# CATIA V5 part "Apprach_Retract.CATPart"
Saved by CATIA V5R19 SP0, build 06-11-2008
Part number: Part1
Bounding box of the stored display mesh (mm): x -48.65 to 48.65, y -48.65 to 48.65, z -9.277 to 47.212
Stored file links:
  G:\Podręcznik\CD\Ruchy pomocnicze\Apprach_Retract.CATPart
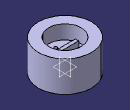
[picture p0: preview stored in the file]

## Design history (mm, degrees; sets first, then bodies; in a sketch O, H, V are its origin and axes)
Body1 (main body)
  Sketch1 on yz-plane, origin (0, 0, 0), H (0, 1, 0), V (0, 0, 1)
    point P1 (0, 21.7369)
    line L1 (0, 21.7369) -> (29.8615, 21.7369)
    line L2 (29.8615, 21.7369) -> (29.8615, 47.2124)
    line L3 (29.8615, 47.2124) -> (48.6633, 47.2124)
    line L4 (48.6633, 47.2124) -> (48.6633, -9.2767)
    line L5 (48.6633, -9.2767) -> (29.8615, -9.2767)
    point P6 (29.8615, -9.2767)
    line L6 (29.8615, -9.2767) -> (29.8615, 8.4454)
    line L7 (29.8615, 8.4454) -> (0, 8.4454)
    point P8 (0, 8.4454)
    line L8 (0, 8.4454) -> (0, 21.7369)
    coincidence: P1 V, P6 L2, P8 V
    horizontal: L1 H, L3 H, L5 H, L7 H
    vertical: L2 V, L4 V, L6 V, L8 V
  Shaft1: profile Sketch1, axis Sketch1.V, angle 360
  Sketch2 on face of Shaft1 from Sketch1.L1, origin (0, 0, 21.7369), H (1, 0, 0), V (0, 1, 0)
    circle A1 centre (0, -16.8434) radius 3.173
    point P1 (0, -16.8434)
    circle A2 centre (0, 16.8434) radius 3.173
    distance V P1 = 0
    symmetry: A1 A2 H
  Pocket1: profile Sketch2, direction (0, 0, -1), through (limit type 6)
  Sketch3 on face of Shaft1 from Sketch1.L1, origin (0, 0, 21.7369), H (1, 0, 0), V (0, 1, 0)
    line L1 (-22.2187, 3) -> (22.6128, 3)
    line L2 (22.6128, 3) -> (22.6128, -3)
    line L3 (22.6128, -3) -> (-22.2187, -3)
    line L4 (-22.2187, -3) -> (-22.2187, 3)
    reference projected circle E1 centre (0, 16.8434) radius 3.173 from edge [face of Shaft1 from Sketch1.L1 | face of Pocket1 from Sketch2.A2]
    length L2 = 6
    radius E1 = 3.173 (reference)
    distance H L1 = 3
    horizontal: L1 H, L3 H
    vertical: L2 V, L4 V
  Pad1: profile Sketch3, direction (0, 0, 1), length 10
Body2
  Sketch4 on yz-plane, origin (0, 0, 0), H (0, 1, 0), V (0, 0, 1)
    point P1 (0, 21.7369)
    line L1 (0, 21.7369) -> (29.8615, 21.7369)
    line L2 (29.8615, 21.7369) -> (29.8615, 47.2124)
    line L3 (29.8615, 47.2124) -> (48.6633, 47.2124)
    line L4 (48.6633, 47.2124) -> (48.6633, -9.2767)
    line L5 (48.6633, -9.2767) -> (29.8615, -9.2767)
    point P6 (29.8615, -9.2767)
    line L6 (29.8615, -9.2767) -> (29.8615, 8.4454)
    line L7 (29.8615, 8.4454) -> (0, 8.4454)
    point P8 (0, 8.4454)
    line L8 (0, 8.4454) -> (0, 21.7369)
    coincidence: P1 V, P6 L2, P8 V
    horizontal: L1 H, L3 H, L5 H, L7 H
    vertical: L2 V, L4 V, L6 V, L8 V
  Shaft2: profile Sketch4, axis Sketch4.V, angle 360
  Sketch5 on face of Shaft2 from Sketch4.L1, origin (0, 0, 21.7369), H (1, 0, 0), V (0, 1, 0)
    line L1 (-22.2187, 3) -> (22.6128, 3)
    line L2 (22.6128, 3) -> (22.6128, -3)
    line L3 (22.6128, -3) -> (-22.2187, -3)
    line L4 (-22.2187, -3) -> (-22.2187, 3)
    length L2 = 6
    distance H L1 = 3
    horizontal: L1 H, L3 H
    vertical: L2 V, L4 V
  Pad2: profile Sketch5, direction (0, 0, 1), length 10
